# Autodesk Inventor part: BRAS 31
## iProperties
Created: 2004-11
Part Number: BRAS 31
Document SubType Name: Modeling
Designer: Bruno
Manufacturer: Standard
Standards Organization: Custom
Author: Bruno
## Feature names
1. Base1
